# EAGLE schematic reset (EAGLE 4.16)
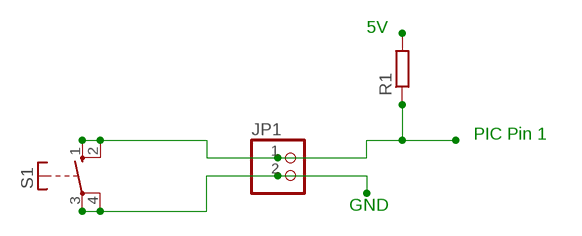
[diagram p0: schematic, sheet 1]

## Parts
JP1  PINHD-1X2  [1X02]
R1  R-EU_0207/5V  [0207/5V]
S1  DT6  [DT6]

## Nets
N$1: JP1.1 R1.1 S1.1(S) S1.2(S)
N$2: R1.2
N$5: JP1.2 S1.3(P) S1.4(P)

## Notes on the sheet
- 5V
- PIC Pin 1
- GND

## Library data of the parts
JP1 = pinhead:PINHD-1X2: PIN HEADER
R1 = rcl:R-EU_: RESISTOR, European symbol
S1 = switch-misc:DT: ITT SWITCH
